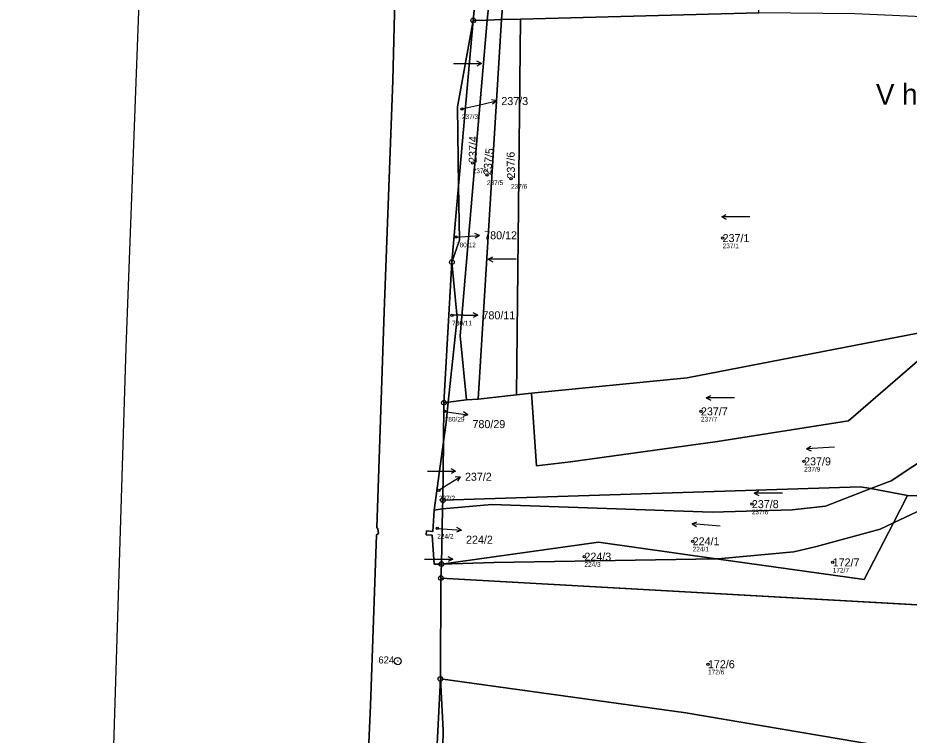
# Model space of a CAD drawing. Extents: x -732749 to -730903, y -1025757 to -1023435.
# Drawn here: x -732690.7 to -732501.5, y -1024211.9 to -1024059.7 of the extents above; entities that cross this region are included whole.
import ezdxf

# ---------------------------------------------------------------- set-up
doc = ezdxf.new("R2010")
doc.units = 0
for name, color, linetype in [('Definiční body', 7, 'Continuous'), ('Hranice parcel', 7, 'Continuous'), ('Parcelní čísla', 7, 'Continuous'), ('Polygon ku', 7, 'Continuous'), ('Polygon parcely', 7, 'Continuous'), ('Pop  PČ popisy', 7, 'Continuous'), ('Značky bodu BP', 7, 'Continuous'), ('Značky kultur', 7, 'Continuous')]:
    doc.layers.add(name, color=color, linetype=linetype)

msp = doc.modelspace()

# ---------------------------------------------------------------- linework, layer by layer
at = {"layer": 'Definiční body'}
for centre in [(-732596.42, -1024079.01), (-732594.13, -1024090.5), (-732591.1, -1024093.02), (-732585.98, -1024093.8), (-732597.68, -1024106.23), (-732541.06, -1024106.43), (-732598.49, -1024122.82), (-732600.08, -1024143.23), (-732545.66, -1024143.21), (-732523.76, -1024153.82), (-732601.31, -1024159.95), (-732534.85, -1024162.89), (-732601.65, -1024168.06), (-732547.42, -1024170.78), (-732570.4, -1024174.04), (-732517.69, -1024175.26), (-732544.17, -1024196.87)]:
    msp.add_circle(centre, 0.25, dxfattribs=at)
at = {"layer": 'Hranice parcel'}
for p, q in [((-732594.01, -1024060.24), (-732591.18, -1024030.91)), ((-732591.02, -1024060.16), (-732589.11, -1024042.07)), ((-732586.54, -1024042.08), (-732588, -1024060.08)), ((-732597.35, -1024078.57), (-732594.01, -1024060.24)), ((-732597.11, -1024095.37), (-732594.01, -1024060.24)), ((-732591.02, -1024060.16), (-732594.01, -1024060.24)), ((-732592.99, -1024140.65), (-732588, -1024060.08)), ((-732588, -1024060.08), (-732591.02, -1024060.16)), ((-732588, -1024060.08), (-732583.96, -1024059.97)), ((-732583.96, -1024059.97), (-732584.81, -1024139.72)), ((-732583.96, -1024059.97), (-732533.37, -1024058.6)), ((-732597.11, -1024095.37), (-732597.35, -1024078.57)), ((-732598.54, -1024111.54), (-732597.11, -1024095.37)), ((-732596.95, -1024106.87), (-732597.11, -1024095.37)), ((-732598.54, -1024111.54), (-732596.95, -1024106.87)), ((-732600.22, -1024141.38), (-732598.54, -1024111.54)), ((-732597.44, -1024123.37), (-732598.54, -1024111.54)), ((-732599.3, -1024141.28), (-732597.44, -1024123.37)), ((-732592.99, -1024140.65), (-732584.81, -1024139.72)), ((-732584.81, -1024139.72), (-732581.62, -1024139.37)), ((-732600.31, -1024149.68), (-732600.22, -1024141.38)), ((-732600.22, -1024141.38), (-732599.3, -1024141.28)), ((-732599.3, -1024141.28), (-732595.43, -1024140.75)), ((-732595.43, -1024140.75), (-732592.99, -1024140.65)), ((-732602.29, -1024164.17), (-732600.31, -1024149.68)), ((-732600.43, -1024162.08), (-732600.31, -1024149.68)), ((-732501.78, -1024161.08), (-732509.6, -1024159.61)), ((-732600.51, -1024163.91), (-732600.43, -1024162.08)), ((-732504.75, -1024166.83), (-732501.78, -1024161.08)), ((-732493.82, -1024161.33), (-732501.78, -1024161.08)), ((-732602.29, -1024164.17), (-732600.51, -1024163.91)), ((-732600.51, -1024163.91), (-732600.76, -1024175.61)), ((-732600.85, -1024178.57), (-732600.76, -1024175.61)), ((-732600.96, -1024200), (-732600.85, -1024178.57)), ((-732475.83, -1024185.64), (-732600.85, -1024178.57)), ((-732601.85, -1024217.92), (-732600.96, -1024200))]:
    msp.add_line(p, q, dxfattribs=at)
for points in [[(-732648.93, -1023739.64), (-732661.12, -1023952.4), (-732662.9, -1024000), (-732667.74, -1024129.74), (-732673.85, -1024325.98), (-732685.48, -1024460.22), (-732686.81, -1024500), (-732690.69, -1024615.98), (-732686.86, -1024774.73)], [(-732617.19, -1024235.86), (-732615.8, -1024205.62), (-732614.56, -1024169.4), (-732614.14, -1024169.15), (-732614.24, -1024168.12), (-732614.5, -1024167.83), (-732612.93, -1024122.07), (-732611.04, -1024072.99), (-732609.95, -1024027.28), (-732608.42, -1023977.58), (-732607.2, -1023938.98), (-732605.88, -1023900.02), (-732603.94, -1023840.25), (-732602.57, -1023798.98), (-732601.55, -1023758.49), (-732599.31, -1023755.8)], [(-732595.43, -1024140.75), (-732596.76, -1024127.2), (-732594.46, -1024099.83), (-732591.02, -1024060.16)], [(-732581.62, -1024139.37), (-732548.62, -1024136.12), (-732490.87, -1024124.9)], [(-732581.62, -1024139.37), (-732580.6, -1024154.76), (-732573.37, -1024153.92), (-732542.13, -1024149.57), (-732514.33, -1024145.21), (-732490.87, -1024124.9)], [(-732478.97, -1024137.96), (-732486.85, -1024145.81), (-732505.29, -1024157.94), (-732509.6, -1024159.61)], [(-732599.3, -1024141.28), (-732599.74, -1024145.55), (-732600.31, -1024149.68)], [(-732509.6, -1024159.61), (-732519.19, -1024163.32), (-732526.27, -1024164.08), (-732543.31, -1024164.62), (-732590.06, -1024162.95), (-732600.51, -1024163.91)], [(-732509.6, -1024159.61), (-732511.81, -1024159.19), (-732600.43, -1024162.08)], [(-732493.82, -1024161.33), (-732496.1, -1024162.75), (-732504.75, -1024166.83)], [(-732600.76, -1024175.61), (-732602.29, -1024175.66), (-732602.69, -1024169.5), (-732603.99, -1024169.42), (-732603.93, -1024168.56), (-732602.6, -1024168.73), (-732602.29, -1024164.17)], [(-732542.45, -1024174.47), (-732541.29, -1024174.45), (-732525.92, -1024172.99), (-732521.16, -1024171.9), (-732507.63, -1024168.18), (-732504.75, -1024166.83)], [(-732542.45, -1024174.47), (-732511.01, -1024178.91), (-732504.75, -1024166.83)], [(-732600.76, -1024175.61), (-732567.44, -1024170.94), (-732542.45, -1024174.47)], [(-732542.45, -1024174.47), (-732589.63, -1024175.27), (-732600.76, -1024175.61)], [(-732600.96, -1024200), (-732600.36, -1024210.85), (-732600.54, -1024218.18)], [(-732483.78, -1024218.21), (-732548.88, -1024207.17), (-732600.96, -1024200)]]:
    msp.add_lwpolyline(points, dxfattribs=at)
at = {"layer": 'Polygon ku'}
msp.add_lwpolyline([(-732394.5, -1023707.84), (-732395.3, -1023708.1), (-732424.5, -1023720.4), (-732456.21, -1023730.35), (-732469.1, -1023734.4), (-732469.3, -1023732.3), (-732470.2, -1023729.8), (-732485.6, -1023738), (-732494.15, -1023742.42), (-732505.9, -1023748.5), (-732521.4, -1023752.2), (-732532.7, -1023753.4), (-732546.6, -1023753.4), (-732555.56, -1023752.87), (-732581.6, -1023747.2), (-732600.8, -1023744.3), (-732601.2, -1023744.26), (-732648.93, -1023739.64), (-732661.12, -1023952.4), (-732662.9, -1024000), (-732667.74, -1024129.74), (-732673.85, -1024325.98)], dxfattribs=at)
at = {"layer": 'Polygon parcely'}
for points in [[(-732617.19, -1024235.86), (-732615.8, -1024205.62), (-732614.56, -1024169.4), (-732614.14, -1024169.15), (-732614.24, -1024168.12), (-732614.5, -1024167.83), (-732612.93, -1024122.07), (-732611.04, -1024072.99), (-732609.95, -1024027.28), (-732608.42, -1023977.58), (-732607.2, -1023938.98), (-732605.88, -1023900.02), (-732603.94, -1023840.25), (-732602.57, -1023798.98), (-732601.55, -1023758.49), (-732599.31, -1023755.8), (-732600.8, -1023744.3), (-732601.2, -1023744.26), (-732648.93, -1023739.64), (-732661.12, -1023952.4), (-732662.9, -1024000), (-732667.74, -1024129.74), (-732673.85, -1024325.98)], [(-732607.2, -1023938.98), (-732608.42, -1023977.58), (-732609.95, -1024027.28), (-732611.04, -1024072.99), (-732612.93, -1024122.07), (-732614.5, -1024167.83), (-732614.24, -1024168.12), (-732614.14, -1024169.15), (-732614.56, -1024169.4), (-732615.8, -1024205.62), (-732617.19, -1024235.86)], [(-732602.29, -1024175.66), (-732602.69, -1024169.5), (-732603.99, -1024169.42), (-732603.93, -1024168.56), (-732602.6, -1024168.73), (-732602.29, -1024164.17), (-732600.31, -1024149.68), (-732600.22, -1024141.38), (-732598.54, -1024111.54), (-732597.11, -1024095.37), (-732597.35, -1024078.57), (-732594.01, -1024060.24), (-732591.18, -1024030.91), (-732590.43, -1024023.02), (-732590.11, -1023986.94), (-732590.82, -1023958.89)], [(-732601.85, -1024217.92), (-732600.96, -1024200), (-732600.85, -1024178.57), (-732600.76, -1024175.61), (-732602.29, -1024175.66)]]:
    msp.add_lwpolyline(points, dxfattribs=at)
for points in [[(-732589.11, -1024042.07), (-732588.68, -1024031.96), (-732591.18, -1024030.91), (-732594.01, -1024060.24), (-732591.02, -1024060.16)], [(-732586.54, -1024042.08), (-732589.11, -1024042.07), (-732591.02, -1024060.16), (-732588, -1024060.08)], [(-732533.2, -1024047.22), (-732554.73, -1024042.21), (-732586.54, -1024042.08), (-732588, -1024060.08), (-732583.96, -1024059.97), (-732533.37, -1024058.6), (-732533.95, -1024047.5), (-732527.44, -1024048.68)], [(-732591.02, -1024060.16), (-732594.01, -1024060.24), (-732597.11, -1024095.37), (-732596.95, -1024106.87), (-732598.54, -1024111.54), (-732597.44, -1024123.37), (-732599.3, -1024141.28), (-732595.43, -1024140.75), (-732596.76, -1024127.2), (-732594.46, -1024099.83)], [(-732594.01, -1024060.24), (-732597.35, -1024078.57), (-732597.11, -1024095.37)], [(-732591.02, -1024060.16), (-732594.46, -1024099.83), (-732596.76, -1024127.2), (-732595.43, -1024140.75), (-732592.99, -1024140.65), (-732588, -1024060.08)], [(-732584.81, -1024139.72), (-732583.96, -1024059.97), (-732588, -1024060.08), (-732592.99, -1024140.65)], [(-732456.19, -1024071.79), (-732433.03, -1024080.66), (-732426.86, -1024071.24), (-732425.3, -1024062.81), (-732495.43, -1024059.65), (-732513.02, -1024058.86), (-732533.37, -1024058.6), (-732583.96, -1024059.97), (-732584.81, -1024139.72), (-732581.62, -1024139.37), (-732548.62, -1024136.12), (-732490.87, -1024124.9), (-732472.63, -1024121.06), (-732471.7, -1024100.62), (-732481.48, -1024099.25), (-732475.75, -1024074.24)], [(-732596.95, -1024106.87), (-732597.11, -1024095.37), (-732598.54, -1024111.54)], [(-732599.3, -1024141.28), (-732597.44, -1024123.37), (-732598.54, -1024111.54), (-732600.22, -1024141.38)], [(-732599.3, -1024141.28), (-732599.74, -1024145.55), (-732600.31, -1024149.68), (-732600.43, -1024162.08), (-732511.81, -1024159.19), (-732509.6, -1024159.61), (-732505.29, -1024157.94), (-732486.85, -1024145.81), (-732478.97, -1024137.96), (-732496.76, -1024134.56), (-732472.63, -1024121.06), (-732490.87, -1024124.9), (-732514.33, -1024145.21), (-732542.13, -1024149.57), (-732573.37, -1024153.92), (-732580.6, -1024154.76), (-732581.62, -1024139.37), (-732584.81, -1024139.72), (-732592.99, -1024140.65), (-732595.43, -1024140.75)], [(-732573.37, -1024153.92), (-732542.13, -1024149.57), (-732514.33, -1024145.21), (-732490.87, -1024124.9), (-732548.62, -1024136.12), (-732581.62, -1024139.37), (-732580.6, -1024154.76)], [(-732505.29, -1024157.94), (-732509.6, -1024159.61), (-732501.78, -1024161.08), (-732493.82, -1024161.33), (-732479.13, -1024152.15), (-732468.34, -1024141.86), (-732466.95, -1024140.1), (-732478.97, -1024137.96), (-732486.85, -1024145.81)], [(-732600.22, -1024141.38), (-732600.31, -1024149.68), (-732599.74, -1024145.55), (-732599.3, -1024141.28)], [(-732600.43, -1024162.08), (-732600.31, -1024149.68), (-732602.29, -1024164.17), (-732600.51, -1024163.91)], [(-732526.27, -1024164.08), (-732543.31, -1024164.62), (-732590.06, -1024162.95), (-732600.51, -1024163.91), (-732600.76, -1024175.61), (-732567.44, -1024170.94), (-732542.45, -1024174.47), (-732541.29, -1024174.45), (-732525.92, -1024172.99), (-732521.16, -1024171.9), (-732507.63, -1024168.18), (-732504.75, -1024166.83), (-732501.78, -1024161.08), (-732509.6, -1024159.61), (-732519.19, -1024163.32)], [(-732511.81, -1024159.19), (-732600.43, -1024162.08), (-732600.51, -1024163.91), (-732590.06, -1024162.95), (-732543.31, -1024164.62), (-732526.27, -1024164.08), (-732519.19, -1024163.32), (-732509.6, -1024159.61)], [(-732469.4, -1024162.08), (-732493.82, -1024161.33), (-732496.1, -1024162.75), (-732504.75, -1024166.83), (-732511.01, -1024178.91), (-732542.45, -1024174.47), (-732589.63, -1024175.27), (-732600.76, -1024175.61), (-732600.85, -1024178.57), (-732475.83, -1024185.64), (-732470.2, -1024164.53)], [(-732493.82, -1024161.33), (-732501.78, -1024161.08), (-732504.75, -1024166.83), (-732496.1, -1024162.75)], [(-732602.29, -1024164.17), (-732602.6, -1024168.73), (-732603.93, -1024168.56), (-732603.99, -1024169.42), (-732602.69, -1024169.5), (-732602.29, -1024175.66), (-732600.76, -1024175.61), (-732600.51, -1024163.91)], [(-732504.75, -1024166.83), (-732507.63, -1024168.18), (-732521.16, -1024171.9), (-732525.92, -1024172.99), (-732541.29, -1024174.45), (-732542.45, -1024174.47), (-732511.01, -1024178.91)], [(-732542.45, -1024174.47), (-732567.44, -1024170.94), (-732600.76, -1024175.61), (-732589.63, -1024175.27)], [(-732475.83, -1024185.64), (-732600.85, -1024178.57), (-732600.96, -1024200), (-732548.88, -1024207.17), (-732483.78, -1024218.21), (-732481.33, -1024210.59), (-732477.69, -1024192.62)], [(-732600.96, -1024200), (-732601.85, -1024217.92), (-732600.54, -1024218.18), (-732600.36, -1024210.85)], [(-732483.78, -1024218.21), (-732548.88, -1024207.17), (-732600.96, -1024200), (-732600.36, -1024210.85), (-732600.54, -1024218.18), (-732560.65, -1024226.06), (-732508.85, -1024235.06), (-732490.3, -1024238.5)]]:
    msp.add_lwpolyline(points, close=True, dxfattribs=at)
at = {"layer": 'Pop  PČ popisy'}
for p, q in [((-732591.97, -1024078.01), (-732589.05, -1024077.34)), ((-732589.05, -1024077.34), (-732590.13, -1024077.07)), ((-732589.05, -1024077.34), (-732589.91, -1024078.05)), ((-732596.42, -1024079.01), (-732591.97, -1024078.01)), ((-732592.67, -1024105.86), (-732593.7, -1024105.43)), ((-732597.68, -1024106.23), (-732595.66, -1024106.07)), ((-732595.66, -1024106.07), (-732592.67, -1024105.86)), ((-732592.67, -1024105.86), (-732593.63, -1024106.43)), ((-732593.04, -1024122.82), (-732594.04, -1024122.32)), ((-732596.04, -1024122.82), (-732598.49, -1024122.82)), ((-732596.04, -1024122.82), (-732593.04, -1024122.82)), ((-732593.04, -1024122.82), (-732594.04, -1024123.32)), ((-732600.08, -1024143.23), (-732598.13, -1024143.51)), ((-732598.13, -1024143.51), (-732595.16, -1024143.93)), ((-732595.16, -1024143.93), (-732596.08, -1024143.29)), ((-732595.16, -1024143.93), (-732596.22, -1024144.28)), ((-732601.31, -1024159.95), (-732599.3, -1024158.68)), ((-732599.3, -1024158.68), (-732596.76, -1024157.09)), ((-732596.76, -1024157.09), (-732597.87, -1024157.2)), ((-732596.76, -1024157.09), (-732597.34, -1024158.05)), ((-732601.65, -1024168.06), (-732599.52, -1024168.23)), ((-732596.53, -1024168.44), (-732597.49, -1024167.87)), ((-732599.52, -1024168.23), (-732596.53, -1024168.44)), ((-732596.53, -1024168.44), (-732597.56, -1024168.87))]:
    msp.add_line(p, q, dxfattribs=at)
at = {"layer": 'Značky bodu BP'}
for centre, radius in [((-732594.01, -1024060.24), 0.5), ((-732594.01, -1024060.24), 0.0303), ((-732598.54, -1024111.54), 0.5), ((-732598.54, -1024111.54), 0.0303), ((-732600.22, -1024141.38), 0.5), ((-732600.22, -1024141.38), 0.0303), ((-732600.43, -1024162.08), 0.5), ((-732600.43, -1024162.08), 0.0303), ((-732600.76, -1024175.61), 0.5), ((-732600.76, -1024175.61), 0.0303), ((-732600.85, -1024178.57), 0.5), ((-732600.85, -1024178.57), 0.0303), ((-732610.04, -1024196.21), 0.75), ((-732610.04, -1024196.21), 0.03), ((-732600.96, -1024200), 0.5), ((-732600.96, -1024200), 0.0303)]:
    msp.add_circle(centre, radius, dxfattribs=at)
at = {"layer": 'Značky kultur'}
for p, q in [((-732598.23, -1024069.42), (-732592.23, -1024069.42)), ((-732592.23, -1024069.42), (-732593.21, -1024068.92)), ((-732592.23, -1024069.42), (-732593.21, -1024069.92)), ((-732541.26, -1024101.92), (-732540.28, -1024101.42)), ((-732535.26, -1024101.92), (-732541.26, -1024101.92)), ((-732541.26, -1024101.92), (-732540.28, -1024102.42)), ((-732590.86, -1024110.94), (-732589.88, -1024110.44)), ((-732584.86, -1024110.94), (-732590.86, -1024110.94)), ((-732590.86, -1024110.94), (-732589.88, -1024111.44)), ((-732544.56, -1024140.33), (-732543.58, -1024139.83)), ((-732538.56, -1024140.33), (-732544.56, -1024140.33)), ((-732544.56, -1024140.33), (-732543.58, -1024140.83)), ((-732523.28, -1024151.13), (-732522.33, -1024150.58)), ((-732517.29, -1024150.82), (-732523.28, -1024151.13)), ((-732523.28, -1024151.13), (-732522.28, -1024151.58)), ((-732603.74, -1024155.89), (-732597.74, -1024155.89)), ((-732597.74, -1024155.89), (-732598.72, -1024155.39)), ((-732597.74, -1024155.89), (-732598.72, -1024156.39)), ((-732534.34, -1024160.58), (-732533.36, -1024160.08)), ((-732528.34, -1024160.58), (-732534.34, -1024160.58)), ((-732534.34, -1024160.58), (-732533.36, -1024161.08)), ((-732547.54, -1024167.08), (-732546.52, -1024166.66)), ((-732541.56, -1024167.6), (-732547.54, -1024167.08)), ((-732547.54, -1024167.08), (-732546.6, -1024167.66)), ((-732604.36, -1024174.57), (-732598.36, -1024174.57)), ((-732598.36, -1024174.57), (-732599.34, -1024174.07)), ((-732598.36, -1024174.57), (-732599.34, -1024175.07))]:
    msp.add_line(p, q, dxfattribs=at)

# ---------------------------------------------------------------- texts
at = {"layer": 'Definiční body'}
for s, p in [('237/3', (-732596.42, -1024081.17)), ('237/4', (-732594.13, -1024092.66)), ('237/5', (-732591.1, -1024095.18)), ('237/6', (-732585.98, -1024095.96)), ('780/12', (-732597.68, -1024108.39)), ('237/1', (-732541.06, -1024108.59)), ('780/11', (-732598.49, -1024124.98)), ('780/29', (-732600.08, -1024145.39)), ('237/7', (-732545.66, -1024145.37)), ('237/9', (-732523.76, -1024155.98)), ('237/2', (-732601.31, -1024162.11)), ('237/8', (-732534.85, -1024165.05)), ('224/2', (-732601.65, -1024170.22)), ('224/1', (-732547.42, -1024172.94)), ('224/3', (-732570.4, -1024176.2)), ('172/7', (-732517.69, -1024177.42)), ('172/6', (-732544.17, -1024199.03))]:
    msp.add_text(s, height=1, dxfattribs=at).set_placement(p)
at = {"layer": 'Parcelní čísla'}
for s, p in [('237/3', (-732588.04, -1024078.21)), ('780/12', (-732591.67, -1024106.69)), ('237/1', (-732541.06, -1024107.28)), ('780/11', (-732592.04, -1024123.67)), ('237/7', (-732545.66, -1024144.06)), ('780/29', (-732594.16, -1024146.76)), ('237/9', (-732523.76, -1024154.67)), ('237/2', (-732595.76, -1024157.93)), ('237/8', (-732534.85, -1024163.74)), ('224/2', (-732595.53, -1024171.29)), ('224/1', (-732547.42, -1024171.63)), ('224/3', (-732570.4, -1024174.89)), ('172/7', (-732517.69, -1024176.11)), ('172/6', (-732544.17, -1024197.72))]:
    msp.add_text(s, height=1.7, dxfattribs=at).set_placement(p)
for s, rotation, p in [('237/4', 89, (-732593.28, -1024090.51)), ('237/5', 84, (-732590.25, -1024093.11)), ('237/6', 91, (-732585.13, -1024093.79))]:
    msp.add_text(s, height=1.7, rotation=rotation, dxfattribs=at).set_placement(p)
at = {"layer": 'Pop  PČ popisy'}
msp.add_text('V hájcích', height=4.4, dxfattribs=at).set_placement((-732508.51, -1024078.12))
at = {"layer": 'Značky bodu BP'}
msp.add_text('624', height=1.5, dxfattribs=at).set_placement((-732614.14, -1024196.71))

doc.saveas('drawing.dxf')
